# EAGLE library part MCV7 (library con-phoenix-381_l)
Mini-Combicon 3.81mm vertikal 7polig (ohne Gegenstecker)
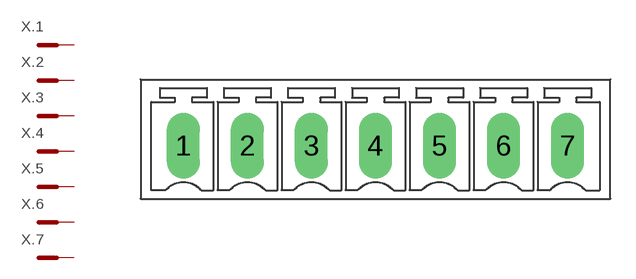
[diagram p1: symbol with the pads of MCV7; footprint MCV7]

Designator prefix X; gates .1=MCST .2=MCST .3=MCST .4=MCST .5=MCST .6=MCST .7=MCST

## MCV7  [MCV7]
1  .1:SK  pas
2  .2:SK  pas
3  .3:SK  pas
4  .4:SK  pas
5  .5:SK  pas
6  .6:SK  pas
7  .7:SK  pas

## Footprint MCV7 (pad centres in mm)
Mini-Combicon 3.81mm vertikal 7-polig (ohne Gegenstecker)
drill 1.3 pad 1.905 long: 1 -11.43,0; 2 -7.62,0; 3 -3.81,0; 4 0,0; 5 3.81,0; 6 7.62,0; 7 11.43,0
